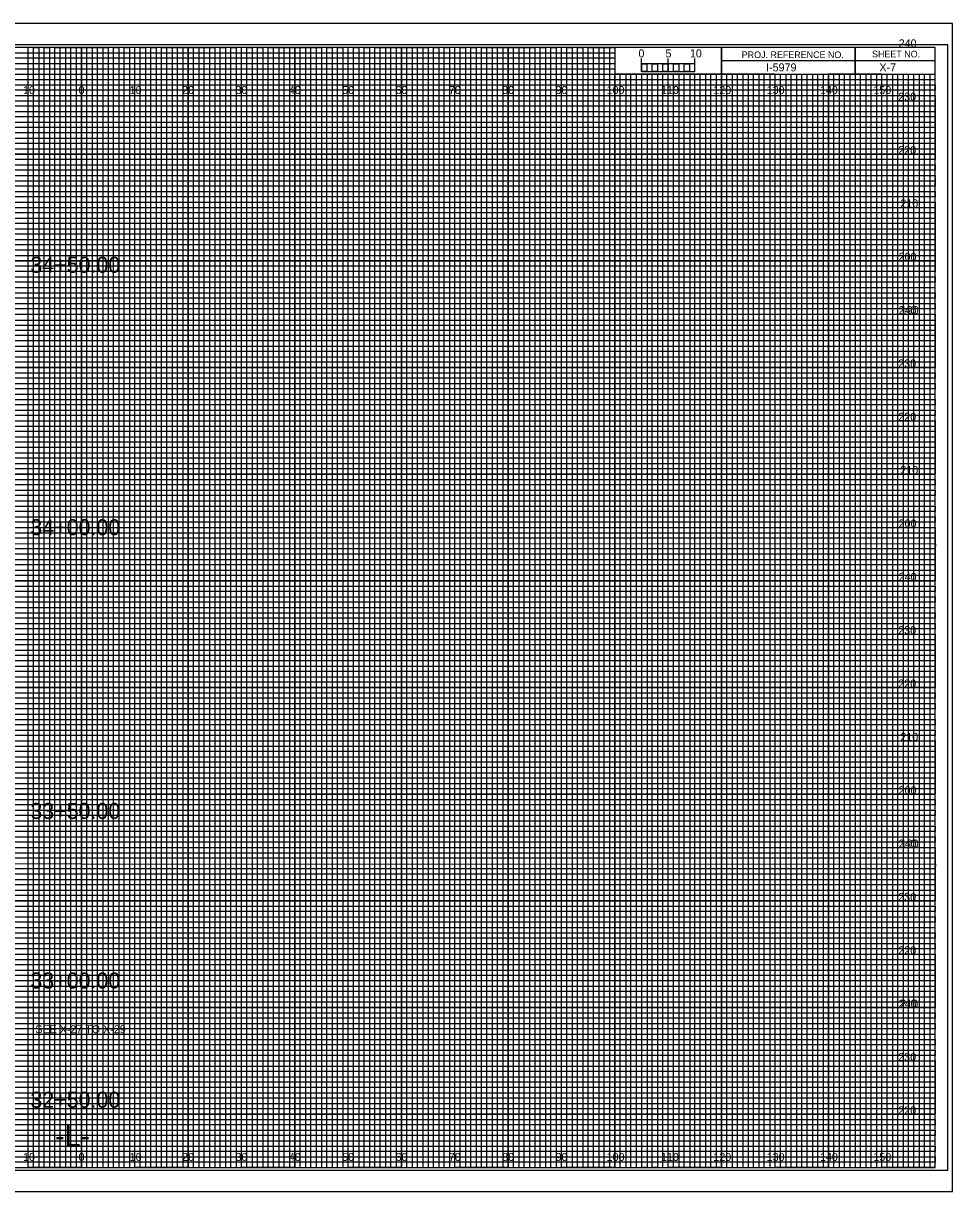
# Model space of a CAD drawing. Extents: x -13 to 359, y -5 to 2854.
# Drawn here: x 149.1 to 323.3, y 1315.5 to 1534.5 of the extents above; entities that cross this region are included whole.
import ezdxf

# ---------------------------------------------------------------- set-up
doc = ezdxf.new("R2010")
doc.units = 0
for name, color, linetype in [('Exist CMT Pavement', 7, 'Continuous'), ('Exist Cross Section Cell', 7, 'Continuous'), ('Exist XS Ground Line', 7, 'Continuous'), ('Prop CMT Conc Surface', 7, 'Continuous'), ('Prop CMT Concrete Structures', 7, 'Continuous'), ('Prop CMT DNC', 7, 'Continuous'), ('Prop CMT Pvmt Course 1', 7, 'Continuous'), ('Prop CMT Pvmt Course 1 CG', 7, 'Continuous'), ('Prop CMT Pvmt Course 1 Wedge', 7, 'Continuous'), ('Prop CMT Pvmt Course 2', 7, 'Continuous'), ('Prop CMT Pvmt Course 2 Wedge', 7, 'Continuous'), ('Prop CMT Pvmt Course 3', 7, 'Continuous'), ('Prop CMT Pvmt Course 3 Wedge', 7, 'Continuous'), ('Prop CMT Pvmt Wedge Surface 3', 7, 'Continuous'), ('Prop CMT Shear Line', 7, 'Continuous'), ('Prop CMT Slope Grass', 7, 'Continuous'), ('Prop CMT Subgrade Earthwork', 7, 'Continuous'), ('Scratch_Level_0', 7, 'Continuous')]:
    doc.layers.add(name, color=color, linetype=linetype)

msp = doc.modelspace()

# ---------------------------------------------------------------- linework, layer by layer
at = {"layer": 'Exist XS Ground Line'}
for p, q in [((150, 1530), (140, 1530)), ((150, 1320), (150, 1530)), ((170, 1530), (160, 1530)), ((160, 1530), (160, 1320)), ((170, 1320), (170, 1530)), ((190, 1530), (180, 1530)), ((180, 1530), (180, 1320)), ((190, 1320), (190, 1530)), ((210, 1530), (200, 1530)), ((200, 1530), (200, 1320)), ((210, 1320), (210, 1530)), ((230, 1530), (220, 1530)), ((220, 1530), (220, 1320)), ((230, 1320), (230, 1530)), ((250, 1530), (240, 1530)), ((240, 1530), (240, 1320)), ((250, 1320), (250, 1530)), ((260, 1530), (260, 1320)), ((270, 1320), (270, 1525)), ((290, 1525), (280, 1525)), ((280, 1525), (280, 1320)), ((290, 1320), (290, 1525)), ((310, 1525), (300, 1525)), ((300, 1525), (300, 1320)), ((310, 1320), (310, 1525)), ((160, 1320), (150, 1320)), ((180, 1320), (170, 1320)), ((200, 1320), (190, 1320)), ((220, 1320), (210, 1320)), ((240, 1320), (230, 1320)), ((260, 1320), (250, 1320)), ((280, 1320), (270, 1320)), ((300, 1320), (290, 1320)), ((320, 1320), (310, 1320)), ((320, 1320), (320, 1320))]:
    msp.add_line(p, q, dxfattribs=at)
for points in [[(0, 1520), (320, 1520), (320, 1510), (0, 1510)], [(0, 1500), (320, 1500), (320, 1490), (0, 1490)], [(0, 1480), (320, 1480), (320, 1470), (0, 1470)], [(0, 1460), (320, 1460), (320, 1450), (0, 1450)], [(0, 1440), (320, 1440), (320, 1430), (0, 1430)], [(0, 1420), (320, 1420), (320, 1410), (0, 1410)], [(0, 1400), (320, 1400), (320, 1390), (0, 1390)], [(0, 1380), (320, 1380), (320, 1370), (0, 1370)], [(0, 1360), (320, 1360), (320, 1350), (0, 1350)], [(0, 1340), (320, 1340), (320, 1330), (0, 1330)]]:
    msp.add_lwpolyline(points, dxfattribs=at)
at = {"layer": 'Prop CMT Conc Surface'}
for p, q in [((265, 1525.49), (265, 1527.9)), ((265, 1526.9), (265, 1527.9)), ((270, 1525.49), (270, 1527.9)), ((275, 1525.49), (275, 1527.9)), ((275, 1526.9), (275, 1527.9))]:
    msp.add_line(p, q, dxfattribs=at)
for points in [[(275, 1526.9), (265, 1526.9), (265, 1525.49), (275, 1525.49)], [(265, 1526.9), (266, 1526.9), (266, 1525.49), (265, 1525.49)], [(267, 1526.9), (268, 1526.9), (268, 1525.49), (267, 1525.49)], [(269, 1526.9), (270, 1526.9), (270, 1525.49), (269, 1525.49)], [(271, 1526.9), (272, 1526.9), (272, 1525.49), (271, 1525.49)], [(273, 1526.9), (274, 1526.9), (274, 1525.49), (273, 1525.49)]]:
    msp.add_lwpolyline(points, close=True, dxfattribs=at)
at = {"layer": 'Prop CMT Concrete Structures'}
for p, q in [((305, 1530), (305, 1525)), ((305, 1525), (305, 1530)), ((280, 1527.5), (280, 1525)), ((320, 1527.49), (280, 1527.49)), ((280, 1525), (320, 1525))]:
    msp.add_line(p, q, dxfattribs=at)
for points in [[(320, 1530), (0, 1530), (0, 1320), (320, 1320)], [(280, 1530), (260, 1530), (260, 1525.03), (280, 1525.03)], [(320, 1530), (280, 1530), (280, 1525), (320, 1525)]]:
    msp.add_lwpolyline(points, close=True, dxfattribs=at)
at = {"layer": 'Prop CMT DNC'}
for p, q in [((323.3, 1534.5), (-13.4, 1534.5)), ((-13.4, 1315.5), (323.3, 1315.5))]:
    msp.add_line(p, q, dxfattribs=at)
at = {"layer": 'Prop CMT Pvmt Course 1'}
for p, q in [((0, 1529), (260, 1529)), ((260, 1529), (260, 1527.98)), ((260, 1527.98), (0, 1527.98)), ((0, 1527), (260, 1527)), ((260, 1527), (260, 1525.89)), ((260, 1525.89), (0, 1525.89)), ((0, 1524), (320, 1524))]:
    msp.add_line(p, q, dxfattribs=at)
for points in [[(0, 1523), (270, 1523), (320, 1523), (320, 1522), (0, 1522)], [(0, 1521), (320, 1521), (320, 1519), (0, 1519)], [(0, 1518), (320, 1518), (320, 1517), (0, 1516.98)], [(0, 1516), (320, 1516), (320, 1514), (0, 1514)], [(0, 1513), (320, 1513), (320, 1512), (0, 1512)], [(0, 1511), (320, 1511), (320, 1509), (0, 1509)], [(0, 1508), (320, 1508), (320, 1507), (0, 1507)], [(0, 1506), (320, 1506), (320, 1504), (0, 1504)], [(0, 1503), (320, 1503), (320, 1502), (0, 1502)], [(0, 1501), (320, 1501), (320, 1499), (0, 1499)], [(0, 1498), (320, 1498), (320, 1497), (0, 1497)], [(0, 1496), (320, 1496), (320, 1493.95), (320, 1493), (320, 1492), (0, 1492)], [(0, 1494), (320, 1494), (320, 1493), (0, 1493)], [(0, 1491), (320, 1491), (320, 1489), (0, 1489.03)], [(0, 1489.03), (320, 1489), (320, 1488), (0, 1488)], [(0, 1487), (320, 1487), (320, 1486), (0, 1486)], [(0, 1484), (320, 1484), (320, 1483), (0, 1483)], [(0, 1482), (320, 1482), (320, 1481), (0, 1481)], [(-0.07, 1478.89), (320, 1478.89), (320, 1477.88), (-0.07, 1477.88)], [(0, 1477), (320, 1477), (320, 1476), (0, 1476)], [(0, 1474), (320, 1474), (320, 1473), (0, 1473)], [(0, 1472), (320, 1472), (320, 1471), (0, 1471)], [(0, 1469), (320, 1469), (320, 1468), (0, 1468)], [(0, 1467), (320, 1467), (320, 1466), (0, 1466)], [(0, 1464), (320, 1464), (320, 1463), (0, 1463)], [(0, 1462), (320, 1462), (320, 1461), (0, 1461)], [(0, 1459), (320, 1459), (319.99, 1457.98), (0, 1458)], [(0, 1457), (320, 1457), (320, 1456), (0, 1456)], [(0, 1454), (320, 1454), (320, 1453), (0, 1453)], [(0, 1452), (320, 1452), (320, 1451), (0, 1451)], [(0, 1449), (320, 1449), (320, 1448), (0, 1448)], [(0, 1447), (320, 1447), (320, 1446), (0, 1446)], [(0, 1444), (320, 1444), (320, 1443), (0, 1443)], [(0, 1442), (320, 1442), (320, 1441), (0, 1441)], [(0, 1439), (320, 1439), (320, 1438), (0, 1438)], [(0, 1436.99), (320.07, 1436.91), (320, 1436), (0, 1436)], [(0, 1434), (320, 1434), (320, 1433), (0, 1433)], [(0, 1432), (320, 1432), (320, 1431), (0, 1431)], [(0, 1429), (320, 1429), (320, 1428), (0, 1428)], [(0, 1427), (320, 1427), (320, 1426), (0, 1426)], [(0, 1424), (320, 1424), (320, 1423), (0, 1423)], [(0, 1422), (320, 1422), (320, 1421), (0, 1421)], [(0, 1419), (320, 1419), (320, 1418), (0, 1418)], [(0, 1417), (320, 1417), (320, 1416), (0, 1416)], [(0, 1414), (320, 1414), (320, 1413), (0, 1413)], [(0, 1412), (320, 1412), (320, 1411), (0, 1411)], [(0, 1409), (320, 1409), (320, 1408), (0, 1408)], [(0, 1407), (320, 1407), (320, 1406), (0, 1406)], [(0, 1404), (320, 1404), (320, 1403), (0, 1403)], [(0, 1402), (320, 1402), (320, 1401), (0, 1401)], [(0, 1399), (320, 1399), (319.99, 1397.98), (0, 1398)], [(0, 1397), (320, 1397), (320, 1396), (0, 1396)], [(0, 1394), (320, 1394), (320, 1393), (0, 1393)], [(0, 1392), (320, 1392), (320, 1391), (0, 1391)], [(0, 1389), (320, 1389), (320, 1388), (0, 1388)], [(0, 1387), (320, 1387), (320, 1386), (0, 1386)], [(0, 1384), (320, 1384), (320, 1383), (0, 1383)], [(0, 1382), (320, 1382), (320, 1381), (0, 1381)], [(0, 1379), (320, 1379), (320, 1378), (0, 1378)], [(0, 1376.99), (320.07, 1376.91), (320, 1376), (0, 1376)], [(0, 1374), (320, 1374), (320, 1373), (0, 1373)], [(0, 1372), (320, 1372), (320, 1371), (0, 1371)], [(0, 1369), (320, 1369), (320, 1368), (0, 1368)], [(0, 1367), (320, 1367), (320, 1366), (0, 1366)], [(0, 1364), (320, 1364), (320, 1363), (0, 1363)], [(0, 1362), (320, 1362), (320, 1361), (0, 1361)], [(0, 1359), (320, 1359), (320, 1358), (0, 1358)], [(0, 1357), (320, 1357), (320, 1356), (0, 1356)], [(0, 1354), (320, 1354), (320, 1353), (0, 1353)], [(0, 1352), (320, 1352), (320, 1351), (0, 1351)], [(0, 1349), (320, 1349), (320, 1348), (0, 1348)], [(0, 1347), (320, 1347), (320, 1346), (0, 1346)], [(0, 1344), (320, 1344), (320, 1343), (0, 1343)], [(0, 1342), (320, 1342), (320, 1341), (0, 1341)], [(0, 1339), (320, 1339), (320, 1338), (0, 1338)], [(0, 1337), (320, 1337), (320, 1336), (0, 1336)], [(0, 1334), (320, 1334), (320, 1333), (0, 1333)], [(0, 1332), (320, 1332), (320, 1331), (0, 1331)], [(0, 1329), (320, 1329), (320, 1328), (0, 1328)], [(0, 1327), (320, 1327), (320, 1326), (0, 1326)], [(0, 1324), (320, 1324), (320, 1323), (0, 1323)], [(0, 1322), (320, 1322), (320, 1321), (0, 1321)]]:
    msp.add_lwpolyline(points, dxfattribs=at)
at = {"layer": 'Prop CMT Pvmt Course 1 CG'}
for p, q in [((267, 1525), (266.01, 1525)), ((266.01, 1525), (266.01, 1320)), ((267, 1320), (267, 1525)), ((269, 1525), (268, 1525)), ((268, 1525), (268, 1320)), ((269, 1320), (269, 1525)), ((266.01, 1320), (265, 1320)), ((268, 1320), (267, 1320))]:
    msp.add_line(p, q, dxfattribs=at)
for points in [[(150, 1320), (151, 1320), (151, 1530), (152, 1530), (152, 1320)], [(152, 1320), (153, 1320), (153, 1530), (154, 1530), (154, 1320)], [(155, 1320), (156, 1320), (156, 1530), (157, 1530), (157, 1320)], [(157, 1320), (158, 1320), (158, 1530), (159, 1530), (159, 1320)], [(160, 1320), (161, 1320), (161, 1530), (162, 1530), (162, 1320)], [(162, 1320), (163, 1320), (163, 1530), (164, 1530), (164, 1320)], [(165, 1320), (166, 1320), (166, 1530), (167, 1530), (167, 1320)], [(167, 1320), (168, 1320), (168, 1530), (169, 1530), (169, 1320)], [(170, 1320), (171, 1320), (171, 1530), (172, 1530), (172, 1320)], [(172, 1320), (173, 1320), (173, 1530), (174, 1530), (174, 1320)], [(175, 1320), (176, 1320), (176, 1530), (177, 1530), (177, 1320)], [(177, 1320), (178, 1320), (178, 1530), (179, 1530), (179, 1320)], [(180, 1320), (181, 1320), (181, 1530), (182, 1530), (182, 1320)], [(182, 1320), (183, 1320), (183, 1530), (184, 1530), (184, 1320)], [(185, 1320), (186, 1320), (186, 1530), (187, 1530), (187, 1320)], [(187, 1320), (188, 1320), (188, 1530), (189, 1530), (189, 1320)], [(190, 1320), (191, 1320), (191, 1530), (192, 1530), (192, 1320)], [(192, 1320), (193, 1320), (193, 1530), (194, 1530), (194, 1320)], [(195, 1320), (196, 1320), (196, 1530), (197, 1530), (197, 1320)], [(197, 1320), (198, 1320), (198, 1530), (199, 1530), (199, 1320)], [(200, 1320), (201, 1320), (201, 1530), (202, 1530), (202, 1320)], [(202, 1320), (203, 1320), (203, 1530), (204, 1530), (204, 1320)], [(205, 1320), (206, 1320), (206, 1530), (207, 1530), (207, 1320)], [(207, 1320), (208, 1320), (208, 1530), (209, 1530), (209, 1320)], [(210, 1320), (211, 1320), (211, 1530), (212, 1530), (212, 1320)], [(212, 1320), (213, 1320), (213, 1530), (214, 1530), (214, 1320)], [(215, 1320), (216, 1320), (216, 1530), (217, 1530), (217, 1320)], [(217, 1320), (218, 1320), (218, 1530), (219, 1530), (219, 1320)], [(220, 1320), (221, 1320), (221, 1530), (222, 1530), (222, 1320)], [(222, 1320), (223, 1320), (223, 1530), (224, 1530), (224, 1320)], [(225, 1320), (226, 1320), (226, 1530), (227, 1530), (227, 1320)], [(227, 1320), (228, 1320), (228, 1530), (229, 1530), (229, 1320)], [(230, 1320), (231, 1320), (231, 1530), (232, 1530), (232, 1320)], [(232, 1320), (233, 1320), (233, 1530), (234, 1530), (234, 1320)], [(235, 1320), (236, 1320), (236, 1530), (237, 1530), (237, 1320)], [(237, 1320), (238, 1320), (238, 1530), (239, 1530), (239, 1320)], [(240, 1320), (241, 1320), (241, 1530), (242, 1530), (242, 1320)], [(242, 1320), (243, 1320), (243, 1530), (244, 1530), (244, 1320)], [(245, 1320), (246, 1320), (246, 1530), (247, 1530), (247, 1320)], [(247, 1320), (248, 1320), (248, 1530), (249, 1530), (249, 1320)], [(250, 1320), (251, 1320), (251, 1530), (252, 1530), (252, 1320)], [(252, 1320), (253, 1320), (253, 1530), (254, 1530), (254, 1320)], [(255, 1320), (256, 1320), (256, 1530), (257, 1530), (257, 1320)], [(257, 1320), (258, 1320), (258, 1530), (259, 1530), (259, 1320)], [(260, 1320), (261, 1320), (261, 1525), (262.02, 1525), (262.02, 1320)], [(262, 1320), (263, 1320), (263, 1525), (263.99, 1525), (263.99, 1320)], [(270, 1320), (270.98, 1320), (270.98, 1525), (272, 1525), (272, 1320)], [(272, 1320), (273, 1320), (273, 1525), (274.05, 1525), (274.05, 1320)], [(275, 1320), (276, 1320), (276, 1525), (277, 1525), (277, 1320)], [(277, 1320), (278, 1320), (278, 1525), (279, 1525), (279, 1320)], [(280, 1320), (281, 1320), (281, 1525), (282, 1525), (282, 1320)], [(282, 1320), (283, 1320), (283, 1525), (284, 1525), (284, 1320)], [(285, 1320), (286, 1320), (286, 1525), (287, 1525), (287, 1320)], [(287, 1320), (288, 1320), (288, 1525), (289, 1525), (289, 1320)], [(290, 1320), (291, 1320), (291, 1525), (292, 1525), (292, 1320)], [(292, 1320), (293, 1320), (293, 1525), (294, 1525), (294, 1320)], [(295, 1320), (296, 1320), (296, 1525), (297, 1525), (297, 1320)], [(297, 1320), (298, 1320), (298, 1525), (299, 1525), (299, 1320)], [(300, 1320), (301, 1320), (301, 1525), (302, 1525), (302, 1320)], [(302, 1320), (303, 1320), (303, 1525), (304, 1525), (304, 1320)], [(305, 1320), (306, 1320), (306, 1525), (307, 1525), (307, 1320)], [(307, 1320), (308, 1320), (308, 1525), (309, 1525), (309, 1320)], [(310, 1320), (311, 1320), (311, 1525), (312, 1525), (312, 1320)], [(312, 1320), (313, 1320), (313, 1525), (314, 1525), (314, 1320)], [(315, 1320), (316, 1320), (316, 1525), (317, 1525), (317, 1320)], [(317, 1320), (318, 1320), (318, 1525), (319, 1525), (319, 1320)]]:
    msp.add_lwpolyline(points, dxfattribs=at)
at = {"layer": 'Prop CMT Shear Line'}
for p, q in [((150, 1320), (150, 1530)), ((160, 1320), (160, 1530)), ((170, 1320), (170, 1530)), ((180, 1320), (180, 1530)), ((190, 1320), (190, 1530)), ((200, 1320), (200, 1530)), ((210, 1320), (210, 1530)), ((220, 1320), (220, 1530)), ((230, 1320), (230, 1530)), ((240, 1320), (240, 1530)), ((250, 1320), (250, 1530)), ((260, 1320), (260, 1524.69)), ((270, 1320), (270, 1524.69)), ((280, 1320), (280, 1524.69)), ((290, 1320), (290, 1524.69)), ((300, 1320), (300, 1524.69)), ((310, 1320), (310, 1524.69)), ((0, 1520), (320, 1520)), ((0, 1510), (320, 1510)), ((0, 1500), (320, 1500)), ((0, 1490), (320, 1490)), ((0, 1480), (320, 1480)), ((0, 1470), (320, 1470)), ((0, 1460), (320, 1460)), ((0, 1450), (320, 1450)), ((0, 1440), (320, 1440)), ((0, 1430), (320, 1430)), ((0, 1420), (320, 1420)), ((0, 1410), (320, 1410)), ((0, 1400), (320, 1400)), ((0, 1390), (320, 1390)), ((0, 1380), (320, 1380)), ((0, 1370), (320, 1370)), ((0, 1360), (320, 1360)), ((0, 1350), (320, 1350)), ((0, 1340), (320, 1340)), ((0, 1330), (320, 1330))]:
    msp.add_line(p, q, dxfattribs=at)
at = {"layer": 'Prop CMT Slope Grass'}
msp.add_lwpolyline([(-10.8, 1319.5), (322.4, 1319.5), (322.4, 1530.5), (-10.8, 1530.5)], close=True, dxfattribs=at)
at = {"layer": 'Prop CMT Subgrade Earthwork'}
msp.add_lwpolyline([(-13.4, 1315.5), (323.3, 1315.5), (323.3, 1534.5), (-13.4, 1534.5)], close=True, dxfattribs=at)
at = {"layer": 'Scratch_Level_0'}
for points in [[(145, 1320), (155, 1320), (155, 1530), (165, 1530), (165, 1320), (175, 1320), (175, 1530), (185, 1530), (185, 1320), (195, 1320), (195, 1530), (205, 1530), (205, 1320), (215, 1320), (215, 1530), (225, 1530), (225, 1320), (235, 1320), (235, 1530), (245, 1530), (245, 1320), (255, 1320), (255, 1530), (259.93, 1530), (260, 1530), (260, 1525), (264.99, 1525), (264.99, 1320), (275, 1320), (275, 1525), (285, 1525), (285, 1320), (295, 1320), (295, 1525), (305, 1525), (305, 1320), (315, 1320), (315, 1525)], [(0, 1525), (275, 1525)], [(0, 1505), (320, 1505), (320, 1515), (0, 1515)], [(0, 1485), (320, 1485), (320, 1495), (0, 1495)], [(0, 1465), (320, 1465), (320, 1475), (0, 1475)], [(0, 1445), (320, 1445), (320, 1455), (0, 1455)], [(0, 1425), (320, 1425), (320, 1435), (0, 1435)], [(0, 1405), (320, 1405), (320, 1415), (0, 1415)], [(0, 1385), (320, 1385), (320, 1395), (0, 1395)], [(0, 1365), (320, 1365), (320, 1375), (0, 1375)], [(0, 1345), (320, 1345), (320, 1355), (0, 1355)], [(0, 1325), (320, 1325), (320, 1335), (0, 1335)]]:
    msp.add_lwpolyline(points, dxfattribs=at)

# ---------------------------------------------------------------- texts
at = {"layer": 'Exist CMT Pavement'}
for s, p in [('5', (269.47, 1528.12)), ('10', (274.04, 1528.12))]:
    msp.add_text(s, height=1.5, dxfattribs=at).set_placement(p)
at = {"layer": 'Exist Cross Section Cell'}
for s, p in [('10', (149.04, 1521.25)), ('0', (159.45, 1521.25)), ('0', (159.45, 1521.25)), ('10', (169.04, 1521.25)), ('20', (178.86, 1521.25)), ('30', (188.86, 1521.25)), ('40', (198.86, 1521.25)), ('50', (208.86, 1521.25)), ('60', (218.86, 1521.25)), ('70', (228.86, 1521.25)), ('80', (238.86, 1521.25)), ('90', (248.86, 1521.25)), ('100', (258.44, 1521.25)), ('110', (268.62, 1521.25)), ('120', (278.44, 1521.25)), ('130', (288.44, 1521.25)), ('140', (298.44, 1521.25)), ('150', (308.44, 1521.25)), ('10', (149.04, 1321.25)), ('0', (159.45, 1321.25)), ('0', (159.45, 1321.25)), ('10', (169.04, 1321.25)), ('20', (178.86, 1321.25)), ('30', (188.86, 1321.25)), ('40', (198.86, 1321.25)), ('50', (208.86, 1321.25)), ('60', (218.86, 1321.25)), ('70', (228.86, 1321.25)), ('80', (238.86, 1321.25)), ('90', (248.86, 1321.25)), ('100', (258.44, 1321.25)), ('110', (268.62, 1321.25)), ('120', (278.44, 1321.25)), ('130', (288.44, 1321.25)), ('140', (298.44, 1321.25)), ('150', (308.44, 1321.25))]:
    msp.add_text(s, height=1.5, dxfattribs=at).set_placement(p)
at = {"layer": 'Prop CMT Conc Surface'}
msp.add_text('0', height=1.5, dxfattribs=at).set_placement((264.41, 1528.12))
at = {"layer": 'Prop CMT Concrete Structures'}
for s, p in [('PROJ. REFERENCE NO.', (283.77, 1527.99)), ('SHEET NO.', (308.19, 1528.12))]:
    msp.add_text(s, height=1.25, dxfattribs=at).set_placement(p)
at = {"layer": 'Prop CMT Pvmt Course 1 Wedge'}
msp.add_text('X-7', height=1.5, dxfattribs=at).set_placement((309.57, 1525.5))
at = {"layer": 'Prop CMT Pvmt Course 2'}
for s, p in [('240', (313.19, 1530)), ('230', (313.11, 1520)), ('220', (313.12, 1510)), ('210', (313.5, 1500)), ('200', (313.17, 1490)), ('240', (313.19, 1480)), ('190', (313.57, 1480)), ('230', (313.11, 1470)), ('220', (313.12, 1460)), ('210', (313.5, 1450)), ('200', (313.17, 1440)), ('240', (313.19, 1430)), ('230', (313.11, 1420)), ('220', (313.12, 1410)), ('210', (313.5, 1400)), ('200', (313.17, 1390)), ('240', (313.19, 1380)), ('190', (313.57, 1380)), ('230', (313.11, 1370)), ('220', (313.12, 1360)), ('240', (313.19, 1350)), ('210', (313.5, 1350)), ('230', (313.11, 1340)), ('220', (313.12, 1330))]:
    msp.add_text(s, height=1.5, dxfattribs=at).set_placement(p)
at = {"layer": 'Prop CMT Pvmt Course 2 Wedge'}
msp.add_text('I-5979', height=1.5, dxfattribs=at).set_placement((288.34, 1525.5))
at = {"layer": 'Prop CMT Pvmt Course 3'}
for s, p in [('34+50.00', (150.41, 1487.75)), ('34+00.00', (150.41, 1438.55)), ('33+50.00', (150.41, 1385.36)), ('33+00.00', (150.41, 1353.58)), ('32+50.00', (150.41, 1331.23))]:
    msp.add_text(s, height=3, dxfattribs=at).set_placement(p)
at = {"layer": 'Prop CMT Pvmt Course 3 Wedge'}
msp.add_text('-L-', height=4, dxfattribs=at).set_placement((155.06, 1324))
at = {"layer": 'Prop CMT Pvmt Wedge Surface 3'}
msp.add_text('SEE X-27 TO X-29', height=1.5, rotation=360, dxfattribs=at).set_placement((151.34, 1345.19))

doc.saveas('drawing.dxf')
